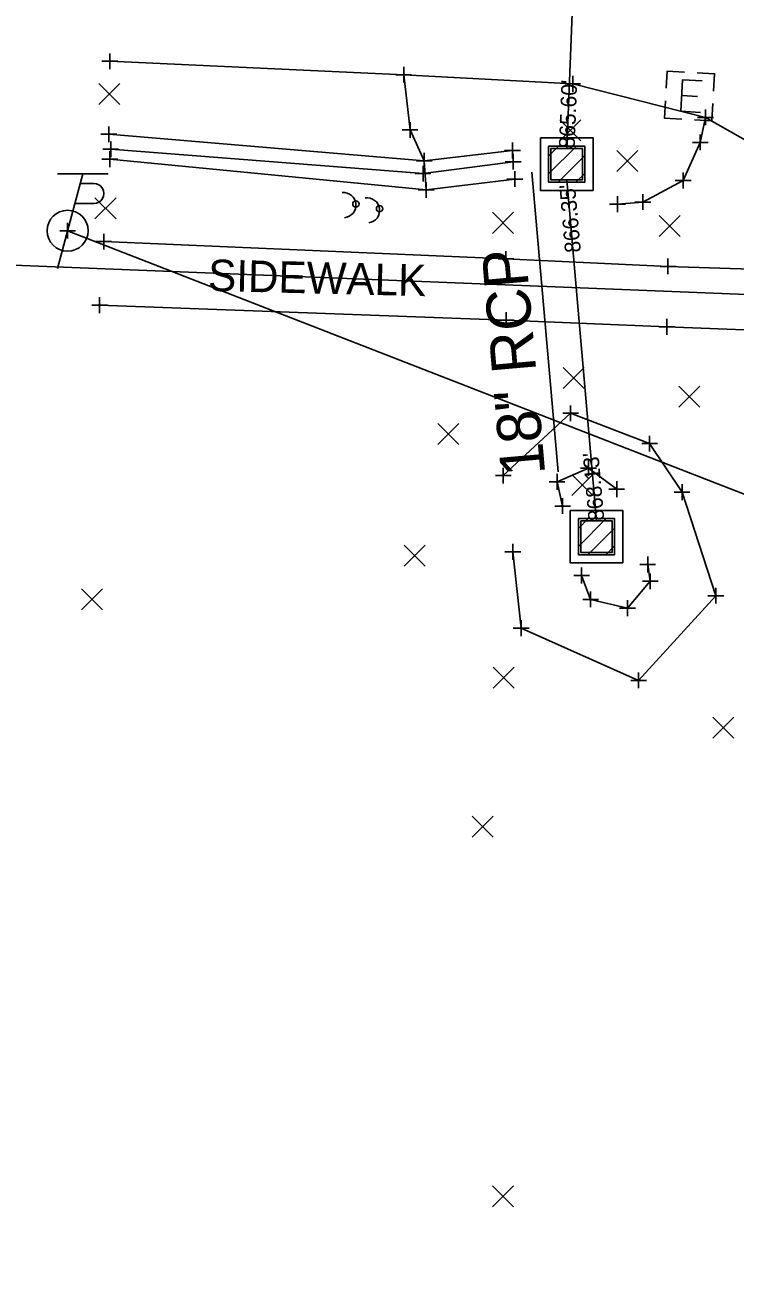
# Model space of a CAD drawing. Extents: x 1380440 to 1381945, y 468756 to 470369.
# Drawn here: x 1381537.8 to 1381582.8, y 470176.8 to 470255.4 of the extents above; entities that cross this region are included whole.
import ezdxf

# ---------------------------------------------------------------- set-up
doc = ezdxf.new("R2010")
doc.units = 0
for name, color, linetype in [('DR_P_Cells', 7, 'Continuous'), ('DR_P_Headwall', 7, 'Continuous'), ('GE_P_Driveway_CL', 7, 'Continuous'), ('PM_X_Cells', 7, 'Continuous'), ('PV_P_Curb', 7, 'Continuous'), ('PV_P_Curb_Ramp', 7, 'Continuous'), ('PV_P_Joint', 7, 'Continuous'), ('PV_P_Parking_Lot', 7, 'Continuous'), ('PV_X_COP', 7, 'Continuous'), ('RW_P_Esmt_TMP', 7, 'Continuous'), ('RW_X_CL', 7, 'Continuous'), ('SC_Scratch1', 7, 'Continuous'), ('SC_Scratch2', 7, 'Continuous'), ('SH_Named_Boundary', 7, 'Continuous'), ('UT_X_Gas', 7, 'Continuous'), ('UT_X_Overhead_Combined', 7, 'Continuous'), ('X-CL', 7, 'Continuous'), ('X-SUBDIVISION', 7, 'Continuous')]:
    doc.layers.add(name, color=color, linetype=linetype)

msp = doc.modelspace()

# ---------------------------------------------------------------- linework, layer by layer
at = {"layer": 'DR_P_Cells'}
for points in [[(1381543.147, 470248.469), (1381563.136, 470246.797), (1381568.729, 470247.446)], [(1381543.21, 470246.894), (1381563.256, 470244.94), (1381568.879, 470245.63)]]:
    msp.add_lwpolyline(points, dxfattribs=at)
at = {"layer": 'DR_P_Headwall'}
for points in [[(1381542.819, 470241.667), (1381568.313, 470240.569), (1381578.584, 470240.095), (1381584.519, 470239.902), (1381590.984, 470239.649), (1381591.472, 470243.585)], [(1381542.564, 470237.64), (1381568.337, 470236.695), (1381578.506, 470236.262), (1381584.487, 470236.02), (1381590.642, 470235.62), (1381587.955, 470203.415), (1381586.625, 470180.461), (1381581.932, 470126.464), (1381577.652, 470073.239), (1381573.197, 470021.541), (1381569.148, 469971.738), (1381565.643, 469929.65), (1381561.644, 469881.156), (1381560.457, 469867.318), (1381559.272, 469848.708), (1381558.347, 469840.136)]]:
    msp.add_lwpolyline(points, dxfattribs=at)
at = {"layer": 'GE_P_Driveway_CL'}
for p, q in [((1381542.519, 470250.365), (1381543.853, 470251.7)), ((1381542.519, 470251.7), (1381543.853, 470250.365)), ((1381571.722, 470248.046), (1381573.056, 470249.381)), ((1381571.722, 470249.381), (1381573.056, 470248.046)), ((1381575.349, 470246.105), (1381576.683, 470247.44)), ((1381575.349, 470247.44), (1381576.683, 470246.105)), ((1381542.267, 470243.114), (1381543.601, 470244.449)), ((1381542.267, 470244.449), (1381543.601, 470243.114)), ((1381567.455, 470242.188), (1381568.789, 470243.523)), ((1381567.455, 470243.523), (1381568.789, 470242.188)), ((1381578.022, 470241.99), (1381579.356, 470243.325)), ((1381578.022, 470243.325), (1381579.356, 470241.99)), ((1381571.942, 470232.36), (1381573.276, 470233.695)), ((1381571.942, 470233.695), (1381573.276, 470232.36)), ((1381579.269, 470231.162), (1381580.603, 470232.497)), ((1381579.269, 470232.497), (1381580.603, 470231.162)), ((1381564, 470228.809), (1381565.334, 470230.144)), ((1381564, 470230.144), (1381565.334, 470228.809)), ((1381572.489, 470225.574), (1381573.823, 470226.909)), ((1381572.489, 470226.909), (1381573.823, 470225.574)), ((1381561.857, 470221.08), (1381563.191, 470222.415)), ((1381561.857, 470222.415), (1381563.191, 470221.08)), ((1381541.417, 470218.315), (1381542.751, 470219.65)), ((1381541.417, 470219.65), (1381542.751, 470218.315)), ((1381567.511, 470213.347), (1381568.845, 470214.682)), ((1381567.511, 470214.682), (1381568.845, 470213.347)), ((1381581.421, 470210.173), (1381582.755, 470211.508)), ((1381581.421, 470211.508), (1381582.755, 470210.173)), ((1381566.179, 470203.905), (1381567.513, 470205.24)), ((1381566.179, 470205.24), (1381567.513, 470203.905)), ((1381567.469, 470180.471), (1381568.803, 470181.806)), ((1381567.469, 470181.806), (1381568.803, 470180.471))]:
    msp.add_line(p, q, dxfattribs=at)
at = {"layer": 'PM_X_Cells'}
for p, q in [((1381579.455, 470250.928), (1381580.453, 470250.871)), ((1381579.954, 470250.9), (1381579.954, 470250.9))]:
    msp.add_line(p, q, dxfattribs=at)
for points in [[(1381579.64, 470252.42), (1381578.542, 470252.483), (1381578.479, 470251.385)], [(1381580.76, 470251.855), (1381579.512, 470251.927), (1381579.398, 470249.93), (1381580.646, 470249.859)], [(1381581.474, 470251.213), (1381581.537, 470252.312), (1381580.439, 470252.374)], [(1381578.434, 470250.586), (1381578.371, 470249.488), (1381579.469, 470249.425)], [(1381580.268, 470249.379), (1381581.366, 470249.317), (1381581.429, 470250.415)]]:
    msp.add_lwpolyline(points, dxfattribs=at)
at = {"layer": 'PV_P_Curb'}
msp.add_lwpolyline([(1381543.263, 470247.518), (1381563.063, 470245.978), (1381568.771, 470246.733)], dxfattribs=at)
at = {"layer": 'PV_P_Curb_Ramp'}
for p, q in [((1381572.166, 470248.243), (1381572.166, 470248.243)), ((1381572.166, 470247.576), (1381572.166, 470247.576)), ((1381571.166, 470246.576), (1381571.166, 470246.576)), ((1381572.166, 470246.576), (1381572.166, 470246.576)), ((1381572.166, 470246.576), (1381572.166, 470246.576)), ((1381572.166, 470246.576), (1381572.166, 470246.576)), ((1381573.166, 470246.576), (1381573.166, 470246.576)), ((1381572.166, 470245.576), (1381572.166, 470245.576)), ((1381572.166, 470244.909), (1381572.166, 470244.909)), ((1381574.054, 470224.623), (1381574.054, 470224.623)), ((1381574.054, 470223.957), (1381574.054, 470223.957)), ((1381573.054, 470222.957), (1381573.054, 470222.957)), ((1381574.054, 470222.957), (1381574.054, 470222.957)), ((1381574.054, 470222.957), (1381574.054, 470222.957)), ((1381574.054, 470222.957), (1381574.054, 470222.957)), ((1381575.054, 470222.957), (1381575.054, 470222.957)), ((1381574.054, 470221.957), (1381574.054, 470221.957)), ((1381574.054, 470221.29), (1381574.054, 470221.29))]:
    msp.add_line(p, q, dxfattribs=at)
at = {"layer": 'PV_P_Joint'}
for p, q in [((1381571.02, 470245.963), (1381572.779, 470247.722)), ((1381571.02, 470247.094), (1381571.648, 470247.722)), ((1381571.619, 470245.43), (1381573.312, 470247.123)), ((1381572.75, 470245.43), (1381573.312, 470245.992)), ((1381572.908, 470222.344), (1381574.667, 470224.102)), ((1381572.908, 470223.475), (1381573.536, 470224.102)), ((1381573.507, 470221.811), (1381575.2, 470223.504)), ((1381574.638, 470221.811), (1381575.2, 470222.372))]:
    msp.add_line(p, q, dxfattribs=at)
for points in [[(1381570.499, 470248.243), (1381573.833, 470248.243), (1381573.833, 470244.909), (1381570.499, 470244.909)], [(1381571.02, 470247.722), (1381573.312, 470247.722), (1381573.312, 470245.43), (1381571.02, 470245.43)], [(1381571.166, 470247.576), (1381573.166, 470247.576), (1381573.166, 470245.576), (1381571.166, 470245.576)], [(1381572.387, 470224.623), (1381575.721, 470224.623), (1381575.721, 470221.29), (1381572.387, 470221.29)], [(1381572.908, 470224.102), (1381575.2, 470224.102), (1381575.2, 470221.811), (1381572.908, 470221.811)], [(1381573.054, 470223.957), (1381575.054, 470223.957), (1381575.054, 470221.957), (1381573.054, 470221.957)]]:
    msp.add_lwpolyline(points, close=True, dxfattribs=at)
at = {"layer": 'PV_P_Parking_Lot'}
msp.add_lwpolyline([(1381568.753, 470221.996), (1381569.282, 470217.157), (1381576.726, 470213.848), (1381581.621, 470219.215), (1381579.474, 470225.779), (1381577.422, 470228.857), (1381572.411, 470230.782), (1381568.146, 470226.829)], dxfattribs=at)
at = {"layer": 'PV_X_COP'}
for p, q in [((1381541.495, 470245.954), (1381539.889, 470239.954)), ((1381543.095, 470245.954), (1381539.895, 470245.954)), ((1381541.335, 470245.354), (1381542.185, 470245.354)), ((1381540.994, 470244.079), (1381542.185, 470244.079))]:
    msp.add_line(p, q, dxfattribs=at)
for centre, radius in [((1381558.804, 470244.052), 0.2), ((1381540.532, 470242.354), 1.3), ((1381560.302, 470243.755), 0.2)]:
    msp.add_circle(centre, radius, dxfattribs=at)
for centre, radius, start, end in [((1381542.198, 470244.717), 0.638, 268.8767, 91.1233), ((1381558.007, 470243.978), 0.8, 275.30795, 95.30795), ((1381559.51, 470243.643), 0.8, 278.10813, 98.10813)]:
    msp.add_arc(centre, radius, start, end, dxfattribs=at)
at = {"layer": 'RW_P_Esmt_TMP'}
for points in [[(1381543.209, 470253.101), (1381561.835, 470252.251), (1381562.236, 470248.747), (1381563.136, 470246.797), (1381563.256, 470244.94), (1381568.879, 470245.63)], [(1381561.835, 470252.251), (1381572.55, 470251.671), (1381580.965, 470249.541)], [(1381575.388, 470244.04), (1381576.993, 470244.172), (1381579.545, 470245.54), (1381580.634, 470247.96), (1381580.965, 470249.541), (1381591.472, 470243.585), (1381595.246, 470241.001), (1381599.724, 470235.672), (1381603.295, 470229.192), (1381604.877, 470222.306), (1381604.1, 470201.731), (1381602.36, 470179.429), (1381598.627, 470125.511), (1381593.594, 470071.886), (1381589.534, 470020.646), (1381585.494, 469971.089), (1381582.039, 469928.84), (1381578.382, 469880.278), (1381576.859, 469862.024), (1381576.832, 469860.709), (1381576.155, 469857.385), (1381571.588, 469847.123), (1381563.138, 469838.251)]]:
    msp.add_lwpolyline(points, dxfattribs=at)
at = {"layer": 'RW_X_CL'}
msp.add_line((1381569.964, 470246.079), (1381571.624, 470227.065), dxfattribs=at)
at = {"layer": 'SC_Scratch2'}
for points in [[(1381571.905, 470224.9), (1381571.558, 470226.436), (1381573.547, 470227.307), (1381575.334, 470225.969)], [(1381577.3, 470221.193), (1381577.462, 470220.133), (1381576.019, 470218.426), (1381573.682, 470218.979), (1381573.112, 470220.499)]]:
    msp.add_lwpolyline(points, dxfattribs=at)
at = {"layer": 'SH_Named_Boundary'}
for p, q in [((1381543.209, 470253.601), (1381543.209, 470252.601)), ((1381542.709, 470253.101), (1381543.709, 470253.101)), ((1381543.209, 470253.101), (1381543.209, 470253.101)), ((1381561.835, 470252.751), (1381561.835, 470251.751)), ((1381561.835, 470252.751), (1381561.835, 470251.751)), ((1381561.335, 470252.251), (1381562.335, 470252.251)), ((1381561.335, 470252.251), (1381562.335, 470252.251)), ((1381561.835, 470252.251), (1381561.835, 470252.251)), ((1381561.835, 470252.251), (1381561.835, 470252.251)), ((1381572.55, 470252.171), (1381572.55, 470251.171)), ((1381572.05, 470251.671), (1381573.05, 470251.671)), ((1381572.55, 470251.671), (1381572.55, 470251.671)), ((1381580.465, 470249.541), (1381581.465, 470249.541)), ((1381580.465, 470249.541), (1381581.465, 470249.541)), ((1381580.465, 470249.541), (1381581.465, 470249.541)), ((1381580.965, 470250.041), (1381580.965, 470249.041)), ((1381580.965, 470250.041), (1381580.965, 470249.041)), ((1381580.965, 470250.041), (1381580.965, 470249.041)), ((1381580.965, 470249.541), (1381580.965, 470249.541)), ((1381580.965, 470249.541), (1381580.965, 470249.541)), ((1381580.965, 470249.541), (1381580.965, 470249.541)), ((1381543.147, 470248.969), (1381543.147, 470247.969)), ((1381562.236, 470249.247), (1381562.236, 470248.247)), ((1381542.647, 470248.469), (1381543.647, 470248.469)), ((1381543.147, 470248.469), (1381543.147, 470248.469)), ((1381543.263, 470248.018), (1381543.263, 470247.018)), ((1381561.736, 470248.747), (1381562.736, 470248.747)), ((1381562.236, 470248.747), (1381562.236, 470248.747)), ((1381580.634, 470248.46), (1381580.634, 470247.46)), ((1381580.634, 470248.46), (1381580.634, 470247.46)), ((1381542.763, 470247.518), (1381543.763, 470247.518)), ((1381543.21, 470247.394), (1381543.21, 470246.394)), ((1381543.263, 470247.518), (1381543.263, 470247.518)), ((1381563.136, 470247.297), (1381563.136, 470246.297)), ((1381563.136, 470247.297), (1381563.136, 470246.297)), ((1381568.229, 470247.446), (1381569.229, 470247.446)), ((1381568.729, 470247.946), (1381568.729, 470246.946)), ((1381568.729, 470247.446), (1381568.729, 470247.446)), ((1381568.771, 470247.233), (1381568.771, 470246.233)), ((1381580.134, 470247.96), (1381581.134, 470247.96)), ((1381580.134, 470247.96), (1381581.134, 470247.96)), ((1381580.634, 470247.96), (1381580.634, 470247.96)), ((1381580.634, 470247.96), (1381580.634, 470247.96)), ((1381542.71, 470246.894), (1381543.71, 470246.894)), ((1381543.21, 470246.894), (1381543.21, 470246.894)), ((1381562.636, 470246.797), (1381563.636, 470246.797)), ((1381562.636, 470246.797), (1381563.636, 470246.797)), ((1381563.063, 470246.478), (1381563.063, 470245.478)), ((1381563.136, 470246.797), (1381563.136, 470246.797)), ((1381563.136, 470246.797), (1381563.136, 470246.797)), ((1381568.271, 470246.733), (1381569.271, 470246.733)), ((1381568.771, 470246.733), (1381568.771, 470246.733)), ((1381562.563, 470245.978), (1381563.563, 470245.978)), ((1381563.063, 470245.978), (1381563.063, 470245.978)), ((1381568.379, 470245.63), (1381569.379, 470245.63)), ((1381568.379, 470245.63), (1381569.379, 470245.63)), ((1381568.879, 470246.13), (1381568.879, 470245.13)), ((1381568.879, 470246.13), (1381568.879, 470245.13)), ((1381568.879, 470245.63), (1381568.879, 470245.63)), ((1381568.879, 470245.63), (1381568.879, 470245.63)), ((1381579.545, 470246.04), (1381579.545, 470245.04)), ((1381562.756, 470244.94), (1381563.756, 470244.94)), ((1381562.756, 470244.94), (1381563.756, 470244.94)), ((1381563.256, 470245.44), (1381563.256, 470244.44)), ((1381563.256, 470245.44), (1381563.256, 470244.44)), ((1381563.256, 470244.94), (1381563.256, 470244.94)), ((1381563.256, 470244.94), (1381563.256, 470244.94)), ((1381579.045, 470245.54), (1381580.045, 470245.54)), ((1381579.545, 470245.54), (1381579.545, 470245.54)), ((1381574.888, 470244.04), (1381575.888, 470244.04)), ((1381575.388, 470244.54), (1381575.388, 470243.54)), ((1381575.388, 470244.04), (1381575.388, 470244.04)), ((1381576.493, 470244.172), (1381577.493, 470244.172)), ((1381576.493, 470244.172), (1381577.493, 470244.172)), ((1381576.993, 470244.672), (1381576.993, 470243.672)), ((1381576.993, 470244.672), (1381576.993, 470243.672)), ((1381576.993, 470244.172), (1381576.993, 470244.172)), ((1381576.993, 470244.172), (1381576.993, 470244.172)), ((1381540.532, 470242.854), (1381540.532, 470241.854)), ((1381540.532, 470242.854), (1381540.532, 470241.854)), ((1381540.032, 470242.354), (1381541.032, 470242.354)), ((1381540.032, 470242.354), (1381541.032, 470242.354)), ((1381540.532, 470242.354), (1381540.532, 470242.354)), ((1381540.532, 470242.354), (1381540.532, 470242.354)), ((1381542.819, 470242.167), (1381542.819, 470241.167)), ((1381542.319, 470241.667), (1381543.319, 470241.667)), ((1381542.819, 470241.667), (1381542.819, 470241.667)), ((1381568.313, 470241.069), (1381568.313, 470240.069)), ((1381567.813, 470240.569), (1381568.813, 470240.569)), ((1381568.313, 470240.569), (1381568.313, 470240.569)), ((1381578.584, 470240.595), (1381578.584, 470239.595)), ((1381578.084, 470240.095), (1381579.084, 470240.095)), ((1381578.584, 470240.095), (1381578.584, 470240.095)), ((1381542.564, 470238.14), (1381542.564, 470237.14)), ((1381542.064, 470237.64), (1381543.064, 470237.64)), ((1381542.564, 470237.64), (1381542.564, 470237.64)), ((1381568.337, 470237.195), (1381568.337, 470236.195)), ((1381567.837, 470236.695), (1381568.837, 470236.695)), ((1381568.337, 470236.695), (1381568.337, 470236.695)), ((1381578.006, 470236.262), (1381579.006, 470236.262)), ((1381578.506, 470236.762), (1381578.506, 470235.762)), ((1381578.506, 470236.262), (1381578.506, 470236.262)), ((1381571.911, 470230.782), (1381572.911, 470230.782)), ((1381572.411, 470231.282), (1381572.411, 470230.282)), ((1381572.411, 470230.782), (1381572.411, 470230.782)), ((1381577.422, 470229.357), (1381577.422, 470228.357)), ((1381577.422, 470229.357), (1381577.422, 470228.357)), ((1381576.922, 470228.857), (1381577.922, 470228.857)), ((1381576.922, 470228.857), (1381577.922, 470228.857)), ((1381577.422, 470228.857), (1381577.422, 470228.857)), ((1381577.422, 470228.857), (1381577.422, 470228.857)), ((1381573.547, 470227.807), (1381573.547, 470226.807)), ((1381567.646, 470226.829), (1381568.646, 470226.829)), ((1381567.646, 470226.829), (1381568.646, 470226.829)), ((1381567.646, 470226.829), (1381568.646, 470226.829)), ((1381568.146, 470227.329), (1381568.146, 470226.329)), ((1381568.146, 470227.329), (1381568.146, 470226.329)), ((1381568.146, 470227.329), (1381568.146, 470226.329)), ((1381568.146, 470226.829), (1381568.146, 470226.829)), ((1381568.146, 470226.829), (1381568.146, 470226.829)), ((1381568.146, 470226.829), (1381568.146, 470226.829)), ((1381571.558, 470226.936), (1381571.558, 470225.936)), ((1381571.558, 470226.936), (1381571.558, 470225.936)), ((1381573.047, 470227.307), (1381574.047, 470227.307)), ((1381573.547, 470227.307), (1381573.547, 470227.307)), ((1381571.058, 470226.436), (1381572.058, 470226.436)), ((1381571.058, 470226.436), (1381572.058, 470226.436)), ((1381571.558, 470226.436), (1381571.558, 470226.436)), ((1381571.558, 470226.436), (1381571.558, 470226.436)), ((1381574.834, 470225.969), (1381575.834, 470225.969)), ((1381574.834, 470225.969), (1381575.834, 470225.969)), ((1381575.334, 470226.469), (1381575.334, 470225.469)), ((1381575.334, 470226.469), (1381575.334, 470225.469)), ((1381575.334, 470225.969), (1381575.334, 470225.969)), ((1381575.334, 470225.969), (1381575.334, 470225.969)), ((1381579.474, 470226.279), (1381579.474, 470225.279)), ((1381571.905, 470225.4), (1381571.905, 470224.4)), ((1381578.974, 470225.779), (1381579.974, 470225.779)), ((1381579.474, 470225.779), (1381579.474, 470225.779)), ((1381571.405, 470224.9), (1381572.405, 470224.9)), ((1381571.905, 470224.9), (1381571.905, 470224.9)), ((1381568.753, 470222.496), (1381568.753, 470221.496)), ((1381568.253, 470221.996), (1381569.253, 470221.996)), ((1381568.753, 470221.996), (1381568.753, 470221.996)), ((1381577.3, 470221.693), (1381577.3, 470220.693)), ((1381572.612, 470220.499), (1381573.612, 470220.499)), ((1381573.112, 470220.999), (1381573.112, 470219.999)), ((1381573.112, 470220.499), (1381573.112, 470220.499)), ((1381576.8, 470221.193), (1381577.8, 470221.193)), ((1381577.3, 470221.193), (1381577.3, 470221.193)), ((1381577.462, 470220.633), (1381577.462, 470219.633)), ((1381577.462, 470220.633), (1381577.462, 470219.633)), ((1381576.962, 470220.133), (1381577.962, 470220.133)), ((1381576.962, 470220.133), (1381577.962, 470220.133)), ((1381577.462, 470220.133), (1381577.462, 470220.133)), ((1381577.462, 470220.133), (1381577.462, 470220.133)), ((1381581.621, 470219.715), (1381581.621, 470218.715)), ((1381581.621, 470219.715), (1381581.621, 470218.715)), ((1381573.182, 470218.979), (1381574.182, 470218.979)), ((1381573.182, 470218.979), (1381574.182, 470218.979)), ((1381573.682, 470219.479), (1381573.682, 470218.479)), ((1381573.682, 470219.479), (1381573.682, 470218.479)), ((1381573.682, 470218.979), (1381573.682, 470218.979)), ((1381573.682, 470218.979), (1381573.682, 470218.979)), ((1381576.019, 470218.926), (1381576.019, 470217.926)), ((1381581.121, 470219.215), (1381582.121, 470219.215)), ((1381581.121, 470219.215), (1381582.121, 470219.215)), ((1381581.621, 470219.215), (1381581.621, 470219.215)), ((1381581.621, 470219.215), (1381581.621, 470219.215)), ((1381575.519, 470218.426), (1381576.519, 470218.426)), ((1381576.019, 470218.426), (1381576.019, 470218.426)), ((1381569.282, 470217.657), (1381569.282, 470216.657)), ((1381569.282, 470217.657), (1381569.282, 470216.657)), ((1381568.782, 470217.157), (1381569.782, 470217.157)), ((1381568.782, 470217.157), (1381569.782, 470217.157)), ((1381569.282, 470217.157), (1381569.282, 470217.157)), ((1381569.282, 470217.157), (1381569.282, 470217.157)), ((1381576.726, 470214.348), (1381576.726, 470213.348)), ((1381576.226, 470213.848), (1381577.226, 470213.848)), ((1381576.726, 470213.848), (1381576.726, 470213.848))]:
    msp.add_line(p, q, dxfattribs=at)
at = {"layer": 'UT_X_Gas'}
msp.add_lwpolyline([(1381485.898, 468926.411), (1381594.271, 470237.893), (1380558.001, 470279.291)], dxfattribs=at)
at = {"layer": 'UT_X_Overhead_Combined'}
msp.add_lwpolyline([(1381540.532, 470242.354), (1381595.795, 470220.833)], dxfattribs=at)
at = {"layer": 'X-CL'}
for p, q in [((1381572.166, 470247.576), (1381573.515, 470281.557)), ((1381574.054, 470223.957), (1381572.166, 470245.576))]:
    msp.add_line(p, q, dxfattribs=at)

# ---------------------------------------------------------------- texts
at = {"layer": 'RW_X_CL'}
msp.add_text('18" RCP', height=2.8, rotation=94.9909, dxfattribs=at).set_placement((1381570.809, 470226.934))
at = {"layer": 'SC_Scratch1'}
for s, rotation, p in [("865.60'", 87.7266, (1381572.666, 470247.556)), ("866.35'", 94.9909, (1381573.067, 470241.005)), ("868.13'", 94.9909, (1381574.552, 470224))]:
    msp.add_text(s, height=1, rotation=rotation, dxfattribs=at).set_placement(p)
at = {"layer": 'X-SUBDIVISION'}
msp.add_text('SIDEWALK', height=2, rotation=358.59482, dxfattribs=at).set_placement((1381549.42, 470238.543))

doc.saveas('drawing.dxf')
